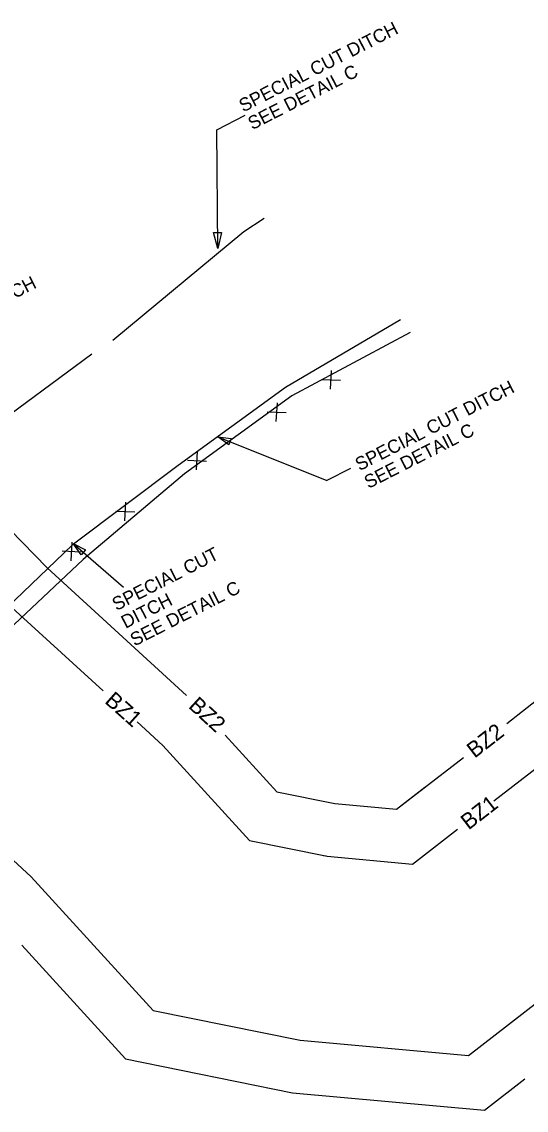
# Model space of a CAD drawing. Extents: x 2384780 to 2405432, y 547869 to 573706.
# Drawn here: x 2404714.2 to 2404904.4, y 571643.7 to 572054.2 of the extents above; entities that cross this region are included whole.
import ezdxf

# ---------------------------------------------------------------- set-up
doc = ezdxf.new("R2010")
doc.units = 0
for name, color, linetype in [('Default', 7, 'Continuous'), ('Old_Level_1', 7, 'Continuous'), ('Old_Level_18', 7, 'Continuous'), ('Old_Level_5', 7, 'Continuous'), ('Old_Level_63', 7, 'Continuous'), ('Prop Buffer Zone 1', 7, 'Continuous'), ('Prop Buffer Zone 2', 7, 'Continuous')]:
    doc.layers.add(name, color=color, linetype=linetype)

# ---------------------------------------------------------------- blocks, each defined once
blk = doc.blocks.new('SPOT')
at = {"layer": 'Old_Level_1'}
for p, q in [((-5.48625, 4.61225), (5.48625, -4.61175)), ((-4.608, -5.326), (4.609, 5.325))]:
    blk.add_line(p, q, dxfattribs=at)

msp = doc.modelspace()

# ---------------------------------------------------------------- linework, layer by layer
at = {"layer": 'Default'}
msp.add_lwpolyline([(2404829.04, 571739.53), (2404828, 571739.61)], dxfattribs=at)
at = {"layer": 'Old_Level_18'}
for points in [[(2404805.67, 571979.98), (2404797.93, 571974.94), (2404748.55, 571933.9)], [(2404857.07, 571941.75), (2404813.67, 571916.17), (2404773.17, 571886.82), (2404733.23, 571856.73), (2404686.77, 571812.42)], [(2404740.65, 571928.82), (2404700.44, 571899.09), (2404659.11, 571870.82)]]:
    msp.add_lwpolyline(points, dxfattribs=at)
at = {"layer": 'Old_Level_5'}
for p, q in [((2404787.77, 572013.46), (2404798.46, 572018.91)), ((2404788.2, 571968.68), (2404787.77, 572013.46)), ((2404788.1, 571897.64), (2404829.26, 571881.19)), ((2404838.17, 571885.73), (2404829.26, 571881.19)), ((2404733.62, 571857.37), (2404752.62, 571840.99))]:
    msp.add_line(p, q, dxfattribs=at)
for points in [[(2404789.5, 571974.73), (2404788.2, 571968.68), (2404786.5, 571974.63)], [(2404792.28, 571894.62), (2404788.1, 571897.64), (2404793.21, 571896.94)], [(2404736.58, 571853.15), (2404733.62, 571857.37), (2404738.22, 571855.03)]]:
    msp.add_lwpolyline(points, close=True, dxfattribs=at)
at = {"layer": 'Old_Level_63'}
msp.add_lwpolyline([(2404860.7, 571937.03), (2404816.02, 571913.12), (2404775.61, 571883.64), (2404737.31, 571851.42), (2404700.54, 571816.85)], dxfattribs=at)
at = {"layer": 'Prop Buffer Zone 1'}
for points in [[(2404892.18, 571760.31), (2404909.24, 571773.54), (2404954.98, 571809.66), (2405020.54, 571854.74), (2405062.12, 571885.27), (2405157.44, 571961.63), (2405160.11, 571964.06)], [(2404709.25, 571834.43), (2404744.9, 571801.79)], [(2404757.7, 571790.09), (2404767.37, 571781.21), (2404800.05, 571745.39), (2404829.35, 571739.47), (2404861.51, 571736.53), (2404878.48, 571749.69)], [(2404855.48, 571757.17), (2404866.22, 571765.49)], [(2404694.7, 571752.75), (2404700.63, 571747.47), (2404717.74, 571731.75), (2404763.75, 571681.31), (2404819.2, 571670.11), (2404882.6, 571664.31), (2404913.92, 571688.59)]]:
    msp.add_lwpolyline(points, dxfattribs=at)
at = {"layer": 'Prop Buffer Zone 2'}
msp.add_line((2404676.79, 571896.3), (2404723.77, 571848.25), dxfattribs=at)
for points in [[(2404897.14, 571789.47), (2404943.11, 571825.77), (2405008.96, 571871.05), (2405049.95, 571901.14), (2405073.47, 571919.98)], [(2404723.77, 571848.25), (2404776.36, 571800.1)], [(2404790.92, 571785.08), (2404810.42, 571763.7), (2404832.25, 571759.29), (2404855.48, 571757.17), (2404880.76, 571776.76)], [(2404714.23, 571705.92), (2404753.38, 571663), (2404816.3, 571650.29), (2404888.63, 571643.68), (2404903.9, 571655.51)]]:
    msp.add_lwpolyline(points, dxfattribs=at)

# ---------------------------------------------------------------- block references
at = {"layer": 'Old_Level_63', "xscale": 0.5, "yscale": 0.5, "rotation": 37.5129687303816}
for p in [(2404830.8, 571919.15), (2404810.37, 571906.95), (2404780.24, 571888.67), (2404753.29, 571869.48), (2404733.03, 571854.42)]:
    msp.add_blockref('SPOT', p, dxfattribs=at)

# ---------------------------------------------------------------- texts
at = {"layer": 'Old_Level_5'}
for s, p in [('SPECIAL CUT DITCH', (2404797.72, 572019.93)), ('SEE DETAIL C', (2404801.12, 572013.24)), ('SPECIAL CUT DITCH', (2404661.28, 571924)), ('SPECIAL CUT DITCH', (2404841.54, 571884.64)), ('SEE DETAIL C', (2404844.94, 571877.95)), ('SPECIAL CUT', (2404749.9, 571831.89)), ('SEE DETAIL C', (2404756.71, 571818.52)), ('DITCH', (2404753.31, 571825.2))]:
    msp.add_text(s, height=5, rotation=26.9999, dxfattribs=at).set_placement(p)
at = {"layer": 'Prop Buffer Zone 1'}
for rotation, p in [(318.2939, (2404745.14, 571797.55)), (37.7887, (2404882.69, 571749.16))]:
    msp.add_text('BZ1', height=6, rotation=rotation, dxfattribs=at).set_placement(p)
at = {"layer": 'Prop Buffer Zone 2'}
for rotation, p in [(317.4341, (2404776.73, 571795.7)), (37.7886, (2404884.96, 571776.23))]:
    msp.add_text('BZ2', height=6, rotation=rotation, dxfattribs=at).set_placement(p)

doc.saveas('drawing.dxf')
